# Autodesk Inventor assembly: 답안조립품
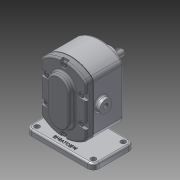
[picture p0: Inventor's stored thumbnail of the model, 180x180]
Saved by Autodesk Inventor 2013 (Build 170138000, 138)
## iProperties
Created: 2019-03
Part Number: 답안조립품
Document SubType Name: Assembly
Designer: Administrator
Author: Administrator
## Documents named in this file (11)
- C:\Users\Administrator\Desktop\490307v1019\답안조립품.iam
- C:\Users\Administrator\Desktop\490307v1019\본체.ipt
- C:\Users\Administrator\Desktop\490307v1019\메인축.ipt
- C:\Users\Administrator\Desktop\490307v1019\키 6 x 6 x 18.ipt
- C:\Users\Administrator\Desktop\490307v1019\스퍼기어.ipt
- C:\Users\Administrator\Desktop\490307v1019\베어링부시.ipt
- C:\Users\Administrator\Desktop\490307v1019\서브축.ipt
- C:\Users\Administrator\Desktop\490307v1019\개스킷.ipt
- C:\Users\Administrator\Desktop\490307v1019\커버.ipt
- C:\Users\Administrator\Desktop\490307v1019\볼트 M5.ipt
- C:\Users\Administrator\Desktop\490307v1019\오일 실 16 28 7.ipt
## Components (1 placed, 1 different names)
1. 개스킷:1
